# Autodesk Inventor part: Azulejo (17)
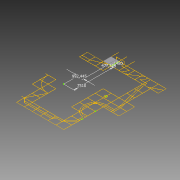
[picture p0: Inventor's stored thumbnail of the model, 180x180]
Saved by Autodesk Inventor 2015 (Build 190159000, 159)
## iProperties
Created: 2015-04
Part Number: Azulejo (17)
Material: Genérico
Document SubType Name: Modeling
Designer: Felipe
Density: 1 g/cm^3
Appearance: Padrão
Author: Felipe
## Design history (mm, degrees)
sketch "Sketch1"
  geometry: L1 (-1510, -7490)-(-1510, -6010); L2 (992.445, 7510)-(992.445, 8990); L3 (1012.445, 7510)-(1012.445, 8990); L4 (-3010, -1490)-(-3010, -10); L5 (-1510, 7490)-(-2990, 7490); L6 (-2990, 10)-(-1510, 10); L7 (-1510, -10)-(-2990, -10); L8 (-1510, -1490)-(-1510, -10); L9 (-10, 9010)-(-10, 10490); L10 (-10, 7510)-(-10, 8990); L11 (-10, 7490)-(-1490, 7490); L12 (-1490, 6010)-(-10, 6010); L13 (-10, 5990)-(-1490, 5990); L14 (-1490, -10)-(-1490, -1490); L15 (-1490, -1490)-(-10, -1490); L16 (-10, -1510)-(-1490, -1510); L17 (-10, -2990)-(-10, -1510); L18 (-10, -5990)-(-10, -4510); L19 (-1490, -7490)-(-10, -7490); L20 (10, 8990)-(10, 7510); L21 (1490, 7510)-(1490, 8990); L22 (10, 6010)-(1490, 6010); L23 (1490, 6010)-(1490, 7490); L24 (1490, 5990)-(10, 5990); L25 (4490, -6010)-(3010, -6010); L26 (10, -1510)-(10, -2990); L27 (10, -3010)-(10, -4490); L28 (10, -4510)-(10, -5990); L29 (10, -5990)-(1490, -5990); L30 (1490, -6010)-(10, -6010); L31 (10, -7490)-(1490, -7490); L32 (2990, 9010)-(2990, 10490); L33 (1510, 8990)-(1510, 7510); L34 (1510, 7510)-(2990, 7510); L35 (2990, 7490)-(1510, 7490); L36 (1510, 7490)-(1510, 6010); L37 (1510, -5990)-(2990, -5990); L38 (2990, -6010)-(1510, -6010); L39 (1510, -7490)-(2990, -7490); L40 (3010, 10490)-(3010, 9010); L41 (3010, 9010)-(4490, 9010); L42 (4490, 8990)-(3010, 8990); L43 (4490, 7490)-(3010, 7490); L44 (4490, 1510)-(4490, 2990); L45 (4490, 10)-(4490, 1490); L46 (4490, -1490)-(4490, -10); L47 (4490, -2990)-(4490, -1510); L48 (3010, -5990)-(4490, -5990); L49 (3010, -7490)-(4490, -7490); L50 (4510, 9010)-(5990, 9010); L51 (5990, 8990)-(4510, 8990); L52 (4510, 7510)-(5990, 7510); L53 (5990, 7490)-(4510, 7490); L54 (4510, 3010)-(5990, 3010); L55 (5990, 2990)-(4510, 2990); L56 (4510, 2990)-(4510, 1510); L57 (4510, 1510)-(5990, 1510); L58 (5990, 1510)-(5990, 1740.185); L59 (5990, 1760.2)-(5990, 2259.8); L60 (5990, 2279.815)-(5990, 2990); L61 (5990, 1490)-(4510, 1490); L62 (4510, 1490)-(4510, 10); L63 (4510, 10)-(5990, 10); L64 (5990, 10)-(5990, 1490)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; A1 r 250 centre (6000, 2010) between (5990, 2259.8) and (5990, 1760.2); A2 r 250 centre (6000, 2010) between (6010, 1760.2) and (6010, 2259.8); A3 r 270 centre (6000, 2010) between (5990, 2279.815) and (5990, 1740.185); A4 r 270 centre (6000, 2010) between (6010, 1740.185) and (6010, 2279.815); A5 r 3010.017 centre (0, 0) between (-1490, -2615.358) and (-346.554, -2990); A6 r 2990.017 centre (0, 0) between (-1490, -2592.316) and (-10, -2990); A7 r 3010.017 centre (0, 0) between (-2603.863, -1510) and (-1510, -2603.863); A8 r 2990.017 centre (0, 0) between (-2580.717, -1510) and (-1510, -2580.717); A9 r 3010.017 centre (0, 0) between (-2990, -346.554) and (-2615.358, -1490); A10 r 2990.017 centre (0, 0) between (-2990, -10) and (-2592.316, -1490); A11 r 2131.367 centre (7500, -1500) between (7490, 631.344) and (6010, 24.017); A12 r 2131.367 centre (7500, -1500) between (5975.983, -10) and (5368.656, -1490); A13 r 2131.367 centre (7500, -1500) between (5368.656, -1510) and (5975.983, -2990); A14 r 2131.367 centre (7500, -1500) between (6010, -3024.017) and (7190, -3608.703); A15 r 1831.367 centre (7500, -1500) between (7490.321, 331.342) and (6463.753, 10); A16 r 1831.367 centre (7500, -1500) between (6435.196, -10) and (6010, -435.196); A17 r 1831.367 centre (7500, -1500) between (5990, -463.753) and (5668.66, -1490); A18 r 1831.367 centre (7500, -1500) between (5668.66, -1510) and (5990, -2536.247); A19 r 1831.367 centre (7500, -1500) between (6010, -2564.804) and (6435.196, -2990); A20 r 1831.367 centre (7500, -1500) between (6463.753, -3010) and (7490, -3331.34); A21 r 2111.367 centre (7500, -1500) between (7490.047, 611.344) and (6024.272, 10); A22 r 2111.367 centre (7500, -1500) between (5990, -24.272) and (5388.656, -1490); A23 r 2111.367 centre (7500, -1500) between (5388.656, -1510) and (5990, -2975.728); A24 r 2111.367 centre (7500, -1500) between (6024.272, -3010) and (7210, -3591.357); A25 r 1811.367 centre (7500, -1500) between (7490.374, 311.342) and (6499.524, 10); A26 r 1811.367 centre (7500, -1500) between (6469.975, -10) and (6010, -469.975); A27 r 1811.367 centre (7500, -1500) between (5990, -499.524) and (5688.66, -1490); A28 r 1811.367 centre (7500, -1500) between (5688.66, -1510) and (5990, -2500.476); A29 r 1811.367 centre (7500, -1500) between (6010, -2530.025) and (6469.975, -2990); A30 r 1811.367 centre (7500, -1500) between (6499.524, -3010) and (7490, -3311.34); A31 r 449.871 centre (7499.449, -4060.672) between (7510, -4510.419) and (7521.546, -4510); 4 further points
  constraints: 1048 end point, 64 point on circle, 31 centre point, 13 point on line, 2 parallel, 1 horizontal, 1 perpendicular, 1 other
  dimensions: "d2" = 7510 distance from line of A5.centre L521; "d3" = 992.4451 distance from line of A8.centre L2; "d4" = 477.5549 distance between parallel lines of L21 L3; "d5" = 1480 distance between parallel lines of L523 L382
extrude "Extrusion1" new body sketch "Sketch1" distance "d0" = 60; taper "d1" = 0 deg
extrude "Extrusion2" new body sketch "Sketch1" distance "d6" = 60; taper "d7" = 0 deg
body "Solid1"
body "Solid2"
